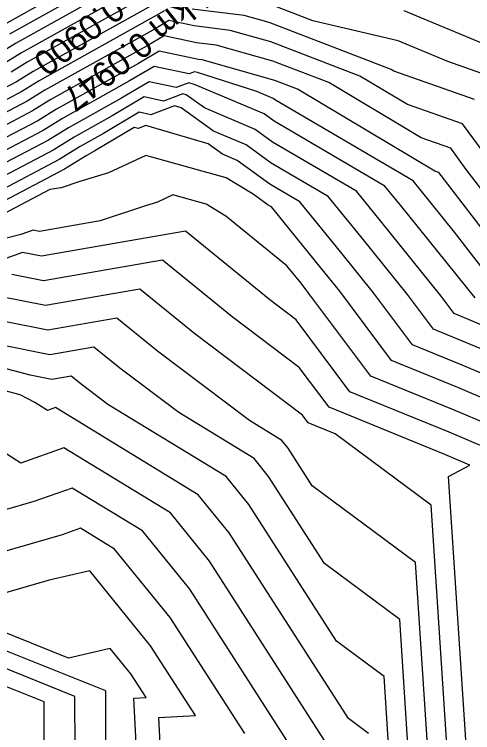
# Model space of a CAD drawing. Extents: x -549394 to -546608, y -1037055 to -1033629.
# Drawn here: x -547219.5 to -547053.3, y -1036274.8 to -1036014.3 of the extents above; entities that cross this region are included whole.
import ezdxf

# ---------------------------------------------------------------- set-up
doc = ezdxf.new("R2010")
doc.units = 0
for name, color, linetype in [('hlavni_vrst', 7, 'Continuous'), ('norm_vrst', 7, 'Continuous'), ('x_popis_pricne_rezy_C411', 7, 'Continuous')]:
    doc.layers.add(name, color=color, linetype=linetype)

msp = doc.modelspace()

# ---------------------------------------------------------------- linework, layer by layer
at = {"layer": 'hlavni_vrst'}
for p, q in [((-547171.43, -1035989.1), (-547223.36, -1036018.08)), ((-547161.94, -1036006.74), (-547212.7, -1036035.07)), ((-547111.22, -1036016.72), (-547127.83, -1036010.31)), ((-547080.24, -1036023.99), (-547111.22, -1036016.72)), ((-547062.3, -1036031.47), (-547080.24, -1036023.99)), ((-547168.82, -1036033.21), (-547177.7, -1036038.46)), ((-547156.15, -1036035.89), (-547168.82, -1036033.21)), ((-547048.3, -1036036.36), (-547062.3, -1036031.47)), ((-547212.7, -1036035.07), (-547218.78, -1036038.81)), ((-547154.16, -1036035.14), (-547156.15, -1036035.89)), ((-547153.11, -1036035.46), (-547154.16, -1036035.14)), ((-547131.51, -1036042.32), (-547153.11, -1036035.46)), ((-547218.78, -1036038.81), (-547242.13, -1036051.11)), ((-547177.7, -1036038.46), (-547202.05, -1036052.05)), ((-547125.59, -1036044.82), (-547131.51, -1036042.32)), ((-547124.74, -1036045.44), (-547125.59, -1036044.82)), ((-547074.84, -1036074.7), (-547124.74, -1036045.44)), ((-547202.05, -1036052.05), (-547209.1, -1036056.41)), ((-547209.1, -1036056.41), (-547236.25, -1036070.69)), ((-547171.78, -1036065.48), (-547185.32, -1036071.84)), ((-547142.72, -1036073.65), (-547171.78, -1036065.48)), ((-547185.32, -1036071.84), (-547195.72, -1036074.9)), ((-547195.72, -1036074.9), (-547202.48, -1036077.18)), ((-547132.86, -1036079.54), (-547142.72, -1036073.65)), ((-547072.26, -1036077.87), (-547074.84, -1036074.7)), ((-547206.64, -1036077.79), (-547230.36, -1036090.28)), ((-547202.48, -1036077.18), (-547206.64, -1036077.79)), ((-547059.82, -1036093.31), (-547072.26, -1036077.87)), ((-547127.44, -1036083.49), (-547132.86, -1036079.54)), ((-547126.27, -1036084.17), (-547127.44, -1036083.49)), ((-547108.3, -1036106.18), (-547126.27, -1036084.17)), ((-547046.99, -1036110.07), (-547059.82, -1036093.31)), ((-547101.47, -1036114.66), (-547108.3, -1036106.18)), ((-547082.66, -1036139.83), (-547101.47, -1036114.66)), ((-547207.41, -1036128.8), (-547228.09, -1036124.77)), ((-547182.34, -1036124.49), (-547207.41, -1036128.8)), ((-547167.65, -1036136.42), (-547182.34, -1036124.49)), ((-547134.25, -1036161.63), (-547167.65, -1036136.42)), ((-547058.66, -1036149.61), (-547082.66, -1036139.83)), ((-547033.64, -1036160.27), (-547058.66, -1036149.61)), ((-547122.45, -1036168.83), (-547134.25, -1036161.63)), ((-547120.18, -1036171.62), (-547122.45, -1036168.83)), ((-547111.44, -1036185.24), (-547120.18, -1036171.62)), ((-547198.53, -1036186.1), (-547212.4, -1036190.97)), ((-547173.02, -1036201.66), (-547198.53, -1036186.1)), ((-547074.04, -1036213.03), (-547111.44, -1036185.24)), ((-547212.4, -1036190.97), (-547223.21, -1036194.11)), ((-547155.85, -1036222.78), (-547173.02, -1036201.66)), ((-547069.17, -1036287.31), (-547074.04, -1036213.03)), ((-547118.07, -1036281.61), (-547155.85, -1036222.78)), ((-547197.57, -1036261.66), (-547233.92, -1036247.04)), ((-547197.5, -1036286.3), (-547197.57, -1036261.66))]:
    msp.add_line(p, q, dxfattribs=at)
at = {"layer": 'norm_vrst'}
for p, q in [((-547167.28, -1035991.38), (-547221.23, -1036021.48)), ((-547163.14, -1035993.65), (-547219.1, -1036024.88)), ((-547159, -1035995.92), (-547216.97, -1036028.27)), ((-547158.79, -1036000.4), (-547214.84, -1036031.67)), ((-547165.09, -1036013.08), (-547210.57, -1036038.46)), ((-547136.12, -1036014.78), (-547155.06, -1036012.44)), ((-547046.87, -1036026.13), (-547078.16, -1036013.09)), ((-547127.13, -1036017.3), (-547136.12, -1036014.78)), ((-547163.44, -1036016.58), (-547168.24, -1036019.43)), ((-547154.26, -1036018.52), (-547163.44, -1036016.58)), ((-547082.87, -1036034.38), (-547127.13, -1036017.3)), ((-547168.24, -1036019.43), (-547208.44, -1036041.86)), ((-547141.22, -1036020.14), (-547154.26, -1036018.52)), ((-547126.44, -1036024.29), (-547141.22, -1036020.14)), ((-547165.23, -1036022.13), (-547171.39, -1036025.77)), ((-547153.47, -1036024.61), (-547165.23, -1036022.13)), ((-547219.1, -1036024.88), (-547224.58, -1036028.26)), ((-547171.39, -1036025.77), (-547206.31, -1036045.26)), ((-547146.33, -1036025.5), (-547153.47, -1036024.61)), ((-547125.74, -1036031.27), (-547146.33, -1036025.5)), ((-547094.17, -1036036.74), (-547126.44, -1036024.29)), ((-547216.97, -1036028.27), (-547222.65, -1036031.78)), ((-547167.03, -1036027.67), (-547174.54, -1036032.12)), ((-547152.67, -1036030.7), (-547167.03, -1036027.67)), ((-547151.43, -1036030.85), (-547152.67, -1036030.7)), ((-547125.05, -1036038.26), (-547151.43, -1036030.85)), ((-547105.47, -1036039.1), (-547125.74, -1036031.27)), ((-547214.84, -1036031.67), (-547220.71, -1036035.3)), ((-547174.54, -1036032.12), (-547204.18, -1036048.65)), ((-547081.89, -1036034.96), (-547082.87, -1036034.38)), ((-547052.6, -1036045.2), (-547081.89, -1036034.96)), ((-547210.57, -1036038.46), (-547216.84, -1036042.33)), ((-547170.62, -1036038.75), (-547180.85, -1036044.81)), ((-547160.77, -1036040.83), (-547170.62, -1036038.75)), ((-547156.25, -1036039.14), (-547160.77, -1036040.83)), ((-547153.89, -1036039.87), (-547156.25, -1036039.14)), ((-547116.77, -1036041.45), (-547125.05, -1036038.26)), ((-547071.96, -1036059.11), (-547105.47, -1036039.1)), ((-547076.93, -1036047.04), (-547094.17, -1036036.74)), ((-547153.89, -1036039.87), (-547153.89, -1036039.87)), ((-547128.86, -1036050.44), (-547153.89, -1036039.87)), ((-547153.89, -1036039.87), (-547153.89, -1036039.87)), ((-547066.99, -1036071.18), (-547116.77, -1036041.45)), ((-547216.84, -1036042.33), (-547240.95, -1036055.02)), ((-547208.44, -1036041.86), (-547214.91, -1036045.85)), ((-547172.41, -1036044.29), (-547184, -1036051.15)), ((-547165.4, -1036045.77), (-547172.41, -1036044.29)), ((-547158.35, -1036043.14), (-547165.4, -1036045.77)), ((-547157.24, -1036043.48), (-547158.35, -1036043.14)), ((-547150.6, -1036048.26), (-547157.24, -1036043.48)), ((-547214.91, -1036045.85), (-547239.78, -1036058.94)), ((-547206.31, -1036045.26), (-547212.97, -1036049.37)), ((-547180.85, -1036044.81), (-547199.92, -1036055.45)), ((-547212.97, -1036049.37), (-547238.6, -1036062.86)), ((-547204.18, -1036048.65), (-547211.04, -1036052.89)), ((-547161.44, -1036047.51), (-547170.02, -1036050.71)), ((-547159.02, -1036048.23), (-547161.44, -1036047.51)), ((-547147.31, -1036056.65), (-547159.02, -1036048.23)), ((-547132.14, -1036056.06), (-547150.6, -1036048.26)), ((-547056.91, -1036054.03), (-547076.93, -1036047.04)), ((-547184, -1036051.15), (-547197.78, -1036058.84)), ((-547174.2, -1036049.83), (-547187.15, -1036057.5)), ((-547170.02, -1036050.71), (-547174.2, -1036049.83)), ((-547125.28, -1036053.05), (-547128.86, -1036050.44)), ((-547211.04, -1036052.89), (-547237.42, -1036066.77)), ((-547171.86, -1036054.62), (-547174.64, -1036055.66)), ((-547149.26, -1036061.27), (-547171.86, -1036054.62)), ((-547085.12, -1036076.6), (-547125.28, -1036053.05)), ((-547046.49, -1036068.33), (-547056.91, -1036054.03)), ((-547199.92, -1036055.45), (-547207.17, -1036059.92)), ((-547176, -1036055.37), (-547190.3, -1036063.84)), ((-547174.64, -1036055.66), (-547176, -1036055.37)), ((-547135.42, -1036061.67), (-547147.31, -1036056.65)), ((-547125.82, -1036060.66), (-547132.14, -1036056.06)), ((-547207.17, -1036059.92), (-547235.07, -1036074.61)), ((-547197.78, -1036058.84), (-547205.23, -1036063.44)), ((-547187.15, -1036057.5), (-547195.65, -1036062.24)), ((-547061.21, -1036062.86), (-547071.96, -1036059.11)), ((-547195.65, -1036062.24), (-547203.3, -1036066.96)), ((-547144.02, -1036065.04), (-547149.26, -1036061.27)), ((-547126.36, -1036068.27), (-547135.42, -1036061.67)), ((-547095.41, -1036078.49), (-547125.82, -1036060.66)), ((-547205.23, -1036063.44), (-547233.89, -1036078.53)), ((-547190.3, -1036063.84), (-547193.52, -1036065.64)), ((-547138.7, -1036067.29), (-547144.02, -1036065.04)), ((-547055.61, -1036070.55), (-547061.21, -1036062.86)), ((-547203.3, -1036066.96), (-547232.71, -1036082.44)), ((-547193.52, -1036065.64), (-547201.37, -1036070.48)), ((-547126.9, -1036075.88), (-547138.7, -1036067.29)), ((-547105.7, -1036080.38), (-547126.36, -1036068.27)), ((-547201.37, -1036070.48), (-547231.54, -1036086.36)), ((-547065.51, -1036071.7), (-547066.99, -1036071.18)), ((-547064.74, -1036072.76), (-547065.51, -1036071.7)), ((-547041.62, -1036102.95), (-547064.74, -1036072.76)), ((-547036.25, -1036095.83), (-547055.61, -1036070.55)), ((-547115.98, -1036082.28), (-547126.9, -1036075.88)), ((-547079.46, -1036083.53), (-547085.12, -1036076.6)), ((-547162.01, -1036079.79), (-547167.64, -1036082.44)), ((-547149.95, -1036083.19), (-547162.01, -1036079.79)), ((-547093.88, -1036094.86), (-547105.7, -1036080.38)), ((-547086.67, -1036089.19), (-547095.41, -1036078.49)), ((-547167.64, -1036082.44), (-547171.95, -1036083.71)), ((-547142.76, -1036087.48), (-547149.95, -1036083.19)), ((-547101.09, -1036100.52), (-547115.98, -1036082.28)), ((-547171.95, -1036083.71), (-547188.34, -1036089.23)), ((-547052.42, -1036117.11), (-547079.46, -1036083.53)), ((-547120.72, -1036105.46), (-547142.76, -1036087.48)), ((-547188.34, -1036089.23), (-547210.45, -1036093.02)), ((-547064.69, -1036116.5), (-547086.67, -1036089.19)), ((-547212.67, -1036092.59), (-547217.14, -1036094.19)), ((-547210.45, -1036093.02), (-547212.67, -1036092.59)), ((-547157.48, -1036093), (-547209.69, -1036101.97)), ((-547126.87, -1036117.85), (-547157.48, -1036093)), ((-547217.14, -1036094.19), (-547232.29, -1036097.92)), ((-547076.95, -1036115.89), (-547093.88, -1036094.86)), ((-547216.52, -1036100.64), (-547230.31, -1036105.55)), ((-547209.69, -1036101.97), (-547216.52, -1036100.64)), ((-547089.21, -1036115.27), (-547101.09, -1036100.52)), ((-547165.77, -1036103.5), (-547208.93, -1036110.91)), ((-547140.46, -1036124.04), (-547165.77, -1036103.5)), ((-547115.51, -1036111.85), (-547120.72, -1036105.46)), ((-547208.93, -1036110.91), (-547220.38, -1036108.68)), ((-547113.74, -1036114.04), (-547115.51, -1036111.85)), ((-547174.06, -1036114), (-547208.17, -1036119.85)), ((-547154.05, -1036130.23), (-547174.06, -1036114)), ((-547090.23, -1036145.49), (-547113.74, -1036114.04)), ((-547208.17, -1036119.85), (-547224.23, -1036116.72)), ((-547075.09, -1036134.17), (-547089.21, -1036115.27)), ((-547067.52, -1036128.5), (-547076.95, -1036115.89)), ((-547059.95, -1036122.84), (-547064.69, -1036116.5)), ((-547117.29, -1036125.08), (-547126.87, -1036117.85)), ((-547116.16, -1036142.38), (-547140.46, -1036124.04)), ((-547097.8, -1036151.15), (-547117.29, -1036125.08)), ((-547053.9, -1036125.3), (-547059.95, -1036122.84)), ((-547047.6, -1036127.99), (-547053.9, -1036125.3)), ((-547115.03, -1036159.69), (-547154.05, -1036130.23)), ((-547055.49, -1036133.41), (-547067.52, -1036128.5)), ((-547206.65, -1036137.74), (-547224.8, -1036134.2)), ((-547190.63, -1036134.99), (-547206.65, -1036137.74)), ((-547181.24, -1036142.61), (-547190.63, -1036134.99)), ((-547057.08, -1036141.51), (-547075.09, -1036134.17)), ((-547042.95, -1036138.75), (-547055.49, -1036133.41)), ((-547213.78, -1036145.14), (-547230.31, -1036140.87)), ((-547159.9, -1036158.72), (-547181.24, -1036142.61)), ((-547105.37, -1036156.82), (-547116.16, -1036142.38)), ((-547038.29, -1036149.51), (-547057.08, -1036141.51)), ((-547205.89, -1036146.68), (-547213.78, -1036145.14)), ((-547198.92, -1036145.49), (-547205.89, -1036146.68)), ((-547194.83, -1036148.8), (-547198.92, -1036145.49)), ((-547060.25, -1036157.72), (-547090.23, -1036145.49)), ((-547217.37, -1036152.31), (-547230.45, -1036148.92)), ((-547185.55, -1036155.81), (-547194.83, -1036148.8)), ((-547061.84, -1036165.82), (-547097.8, -1036151.15)), ((-547212.13, -1036155.02), (-547217.37, -1036152.31)), ((-547207.53, -1036157.95), (-547212.13, -1036155.02)), ((-547142.68, -1036181.96), (-547185.55, -1036155.81)), ((-547204.6, -1036156.93), (-547207.53, -1036157.95)), ((-547152.79, -1036188.53), (-547204.6, -1036156.93)), ((-547132.56, -1036175.4), (-547159.9, -1036158.72)), ((-547063.42, -1036173.92), (-547105.37, -1036156.82)), ((-547028.99, -1036171.02), (-547060.25, -1036157.72)), ((-547112.94, -1036162.48), (-547115.03, -1036159.69)), ((-547103.2, -1036166.45), (-547112.94, -1036162.48)), ((-547068.37, -1036192.34), (-547103.2, -1036166.45)), ((-547024.33, -1036181.78), (-547061.84, -1036165.82)), ((-547217.22, -1036177.01), (-547226.03, -1036171.38)), ((-547201.57, -1036171.51), (-547217.22, -1036177.01)), ((-547162.9, -1036195.1), (-547201.57, -1036171.51)), ((-547054.32, -1036177.8), (-547063.42, -1036173.92)), ((-547127.32, -1036181.85), (-547132.56, -1036175.4)), ((-547062.02, -1036181.85), (-547054.32, -1036177.8)), ((-547134.45, -1036192.08), (-547142.68, -1036181.96)), ((-547107.06, -1036213.39), (-547127.32, -1036181.85)), ((-547055.19, -1036285.88), (-547062.02, -1036181.85)), ((-547141.58, -1036202.31), (-547152.79, -1036188.53)), ((-547102.69, -1036241.55), (-547134.45, -1036192.08)), ((-547062.18, -1036286.6), (-547068.37, -1036192.34)), ((-547148.72, -1036212.54), (-547162.9, -1036195.1)), ((-547202.22, -1036203.05), (-547227.82, -1036210.48)), ((-547195.49, -1036200.69), (-547202.22, -1036203.05)), ((-547183.13, -1036208.23), (-547195.49, -1036200.69)), ((-547098.31, -1036269.7), (-547141.58, -1036202.31)), ((-547162.98, -1036233.01), (-547183.13, -1036208.23)), ((-547100.17, -1036288.14), (-547148.72, -1036212.54)), ((-547079.72, -1036233.71), (-547107.06, -1036213.39)), ((-547192.19, -1036216.09), (-547206.86, -1036219.43)), ((-547170.12, -1036243.24), (-547192.19, -1036216.09)), ((-547206.86, -1036219.43), (-547232.43, -1036226.86)), ((-547199.85, -1036247.75), (-547233.24, -1036234.32)), ((-547135.97, -1036275.08), (-547162.98, -1036233.01)), ((-547076.15, -1036288.03), (-547079.72, -1036233.71)), ((-547186.37, -1036259.67), (-547233.58, -1036240.68)), ((-547085.4, -1036254.39), (-547102.69, -1036241.55)), ((-547184.71, -1036244.3), (-547199.85, -1036247.75)), ((-547177.25, -1036253.47), (-547184.71, -1036244.3)), ((-547153.86, -1036268.55), (-547170.12, -1036243.24)), ((-547208.76, -1036263.66), (-547234.26, -1036253.4)), ((-547171.76, -1036262.02), (-547177.25, -1036253.47)), ((-547083.14, -1036288.74), (-547085.4, -1036254.39)), ((-547186.29, -1036291.65), (-547186.37, -1036259.67)), ((-547176.23, -1036262.27), (-547171.76, -1036262.02)), ((-547175.12, -1036282.28), (-547176.23, -1036262.27)), ((-547208.71, -1036280.94), (-547208.76, -1036263.66)), ((-547167.1, -1036269.29), (-547153.86, -1036268.55)), ((-547165.47, -1036298.6), (-547167.1, -1036269.29)), ((-547091.07, -1036275.08), (-547098.31, -1036269.7))]:
    msp.add_line(p, q, dxfattribs=at)

# ---------------------------------------------------------------- texts
at = {"layer": 'x_popis_pricne_rezy_C411'}
for s, p in [('PŘ 4 km 0.0900', (-547145.23, -1035976.05)), ('PŘ 5 km 0.0947', (-547134.98, -1035988.95))]:
    msp.add_text(s, height=9.0627, rotation=218.4742, dxfattribs=at).set_placement(p)

doc.saveas('drawing.dxf')
